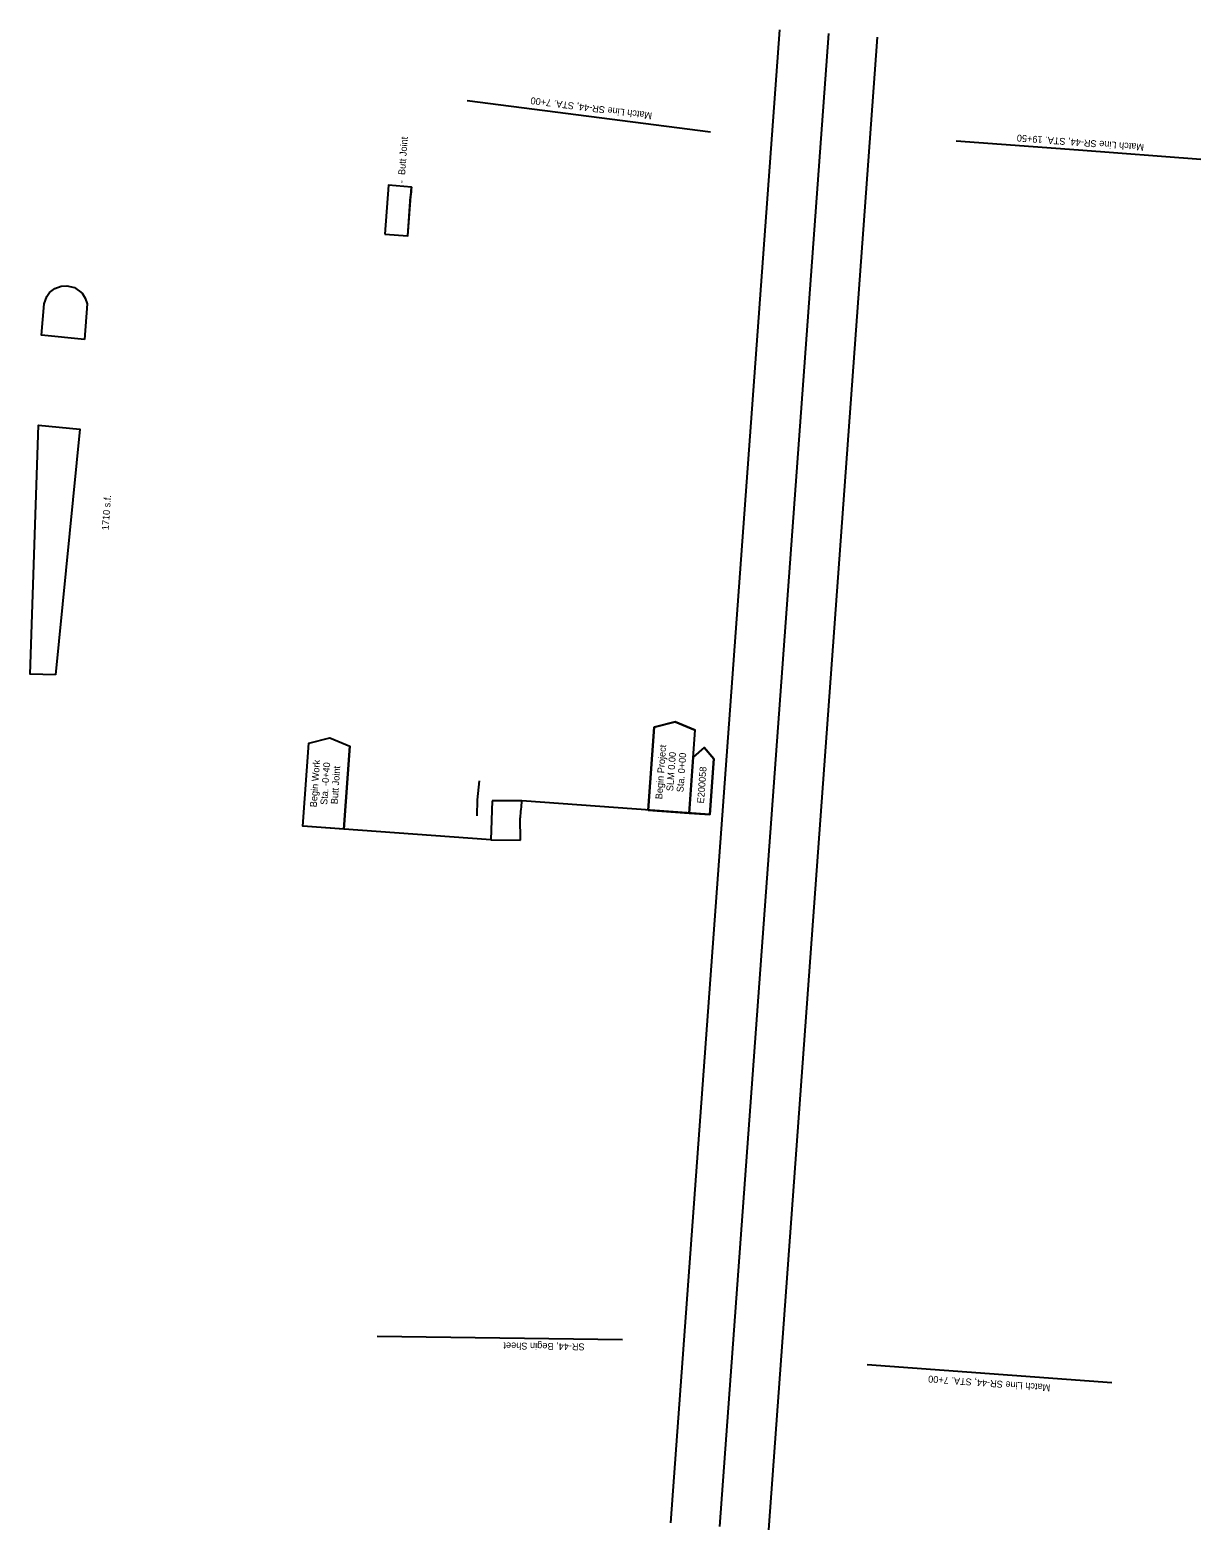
# Model space of a CAD drawing. Extents: x -629 to 938, y 589 to 1985.
# Drawn here: x 461 to 938, y 1245 to 1856 of the extents above; entities that cross this region are included whole.
import ezdxf

# ---------------------------------------------------------------- set-up
doc = ezdxf.new("R2010")
doc.units = 0
for name, color, linetype in [('DR_P_Culvert', 7, 'Continuous'), ('GK_Clip_Borders', 7, 'Continuous'), ('PM_P_Channelizing_Line', 7, 'Continuous'), ('PM_X_Island', 7, 'Continuous'), ('PV_P_Shoulder', 7, 'Continuous'), ('PV_X_Curb', 7, 'Continuous'), ('RD_X_GR_Lt', 7, 'Continuous'), ('RD_X_GR_Rt', 7, 'Continuous'), ('RS_Raster1', 7, 'Continuous')]:
    doc.layers.add(name, color=color, linetype=linetype)

msp = doc.modelspace()

# ---------------------------------------------------------------- linework, layer by layer
at = {"layer": 'DR_P_Culvert'}
for points in [[(605.38, 1772.72), (614.69, 1772.04), (616.21, 1791.89), (606.83, 1792.63)], [(712.59, 1537.98), (729.34, 1536.76), (731.81, 1570.58), (723.63, 1573.99), (715.05, 1571.81)], [(588.66, 1530.19), (571.91, 1531.41), (574.37, 1565.23), (582.95, 1567.41), (591.12, 1564.01)], [(729.34, 1536.76), (737.72, 1536.15), (739.38, 1558.93), (735.49, 1563.42), (731, 1559.54)]]:
    msp.add_lwpolyline(points, close=True, dxfattribs=at)
at = {"layer": 'GK_Clip_Borders'}
for points in [[(738.04, 1814.32), (688.45, 1820.66), (638.85, 1827)], [(937.84, 1803.18), (887.98, 1806.9), (838.11, 1810.63)], [(702.17, 1322.1), (652.18, 1322.77), (602.18, 1323.43)], [(901.51, 1304.58), (851.65, 1308.24), (801.78, 1311.89)]]:
    msp.add_lwpolyline(points, dxfattribs=at)
at = {"layer": 'PM_P_Channelizing_Line'}
for points in [[(483, 1729.79), (465.47, 1731.47), (466.53, 1744.33), (467.57, 1747.22), (468.76, 1748.85), (470.89, 1750.54), (473.46, 1751.52), (475.8, 1751.69), (478.93, 1750.91), (481.98, 1748.63), (483.3, 1746.58), (484.02, 1744.23)], [(471.12, 1593.15), (460.77, 1593.39), (464.3, 1694.83), (481.09, 1693.25)]]:
    msp.add_lwpolyline(points, close=True, dxfattribs=at)
at = {"layer": 'PV_P_Shoulder'}
msp.add_line((741.84, 1246.05), (786.16, 1854.44), dxfattribs=at)
at = {"layer": 'PV_X_Curb'}
for p, q in [((721.89, 1247.5), (766.21, 1855.89)), ((761.79, 1244.6), (806.11, 1852.98))]:
    msp.add_line(p, q, dxfattribs=at)
at = {"layer": 'RD_X_GR_Lt'}
for p, q in [((712.59, 1537.98), (715.05, 1571.81)), ((571.91, 1531.41), (574.37, 1565.23)), ((729.34, 1536.76), (731.81, 1570.58)), ((588.66, 1530.19), (591.12, 1564.01)), ((735.49, 1563.42), (731, 1559.54)), ((735.49, 1563.42), (739.38, 1558.93))]:
    msp.add_line(p, q, dxfattribs=at)
for points in [[(715.05, 1571.81), (723.63, 1573.99), (731.81, 1570.58)], [(574.37, 1565.23), (582.95, 1567.41), (591.12, 1564.01)], [(739.38, 1558.93), (737.72, 1536.15), (729.34, 1536.76), (731, 1559.54)], [(737.72, 1536.15), (661.08, 1541.74)], [(648.55, 1525.82), (571.91, 1531.41)]]:
    msp.add_lwpolyline(points, dxfattribs=at)
at = {"layer": 'RD_X_GR_Rt'}
for p, q in [((606.83, 1792.63), (605.38, 1772.72)), ((616.21, 1791.89), (606.83, 1792.63)), ((614.69, 1772.04), (615.84, 1788.05)), ((605.38, 1772.72), (614.69, 1772.04)), ((649.02, 1541.74), (648.55, 1525.82)), ((661.08, 1541.74), (649.02, 1541.74)), ((660.55, 1525.66), (660.43, 1534.86)), ((648.55, 1525.82), (660.55, 1525.66))]:
    msp.add_line(p, q, dxfattribs=at)
for centre, major_axis, ratio in [((742.41, 1778.07), (-67.28, -107.92), 0.997947), ((887.41, 1516.78), (-120.47, -193.23), 0.999992)]:
    msp.add_ellipse(centre, major_axis=major_axis, ratio=ratio, start_param=5.160044, end_param=5.190378, dxfattribs=at)
at = {"layer": 'RS_Raster1'}
msp.add_lwpolyline([(642.9, 1535.58), (643.11, 1542.16), (643.85, 1549.97)], dxfattribs=at)

# ---------------------------------------------------------------- texts
at = {"layer": 'GK_Clip_Borders'}
for s, rotation, p in [('Match Line SR-44, STA. 7+00', 172.71851, (714.34, 1822.21)), ('Match Line SR-44, STA. 19+50', 175.72759, (914.71, 1809.43)), ('E200058', 85.83338, (735.34, 1540.62)), ('SR-44, Begin Sheet', 179.23937, (686.76, 1320.6)), ('Match Line SR-44, STA. 7+00', 175.80633, (876.51, 1303.9))]:
    msp.add_text(s, height=2.8, rotation=rotation, dxfattribs=at).set_placement(p)
at = {"layer": 'PM_X_Island'}
msp.add_text('1710 s.f.', height=2.8, rotation=85.83333, dxfattribs=at).set_placement((492.78, 1651.93))
at = {"layer": 'RD_X_GR_Lt'}
for s, p in [('-  Butt Joint', (613.32, 1793.4)), (' Begin Project', (718.26, 1541.28)), (' SLM 0.00', (722.72, 1544.57)), (' Sta. 0+00', (726.89, 1544.13)), (' Begin Work', (577.48, 1538.02)), (' Sta. -0+40', (581.77, 1538.99)), (' Butt Joint', (586, 1539.26))]:
    msp.add_text(s, height=2.8, rotation=85.83338, dxfattribs=at).set_placement(p)

doc.saveas('drawing.dxf')
